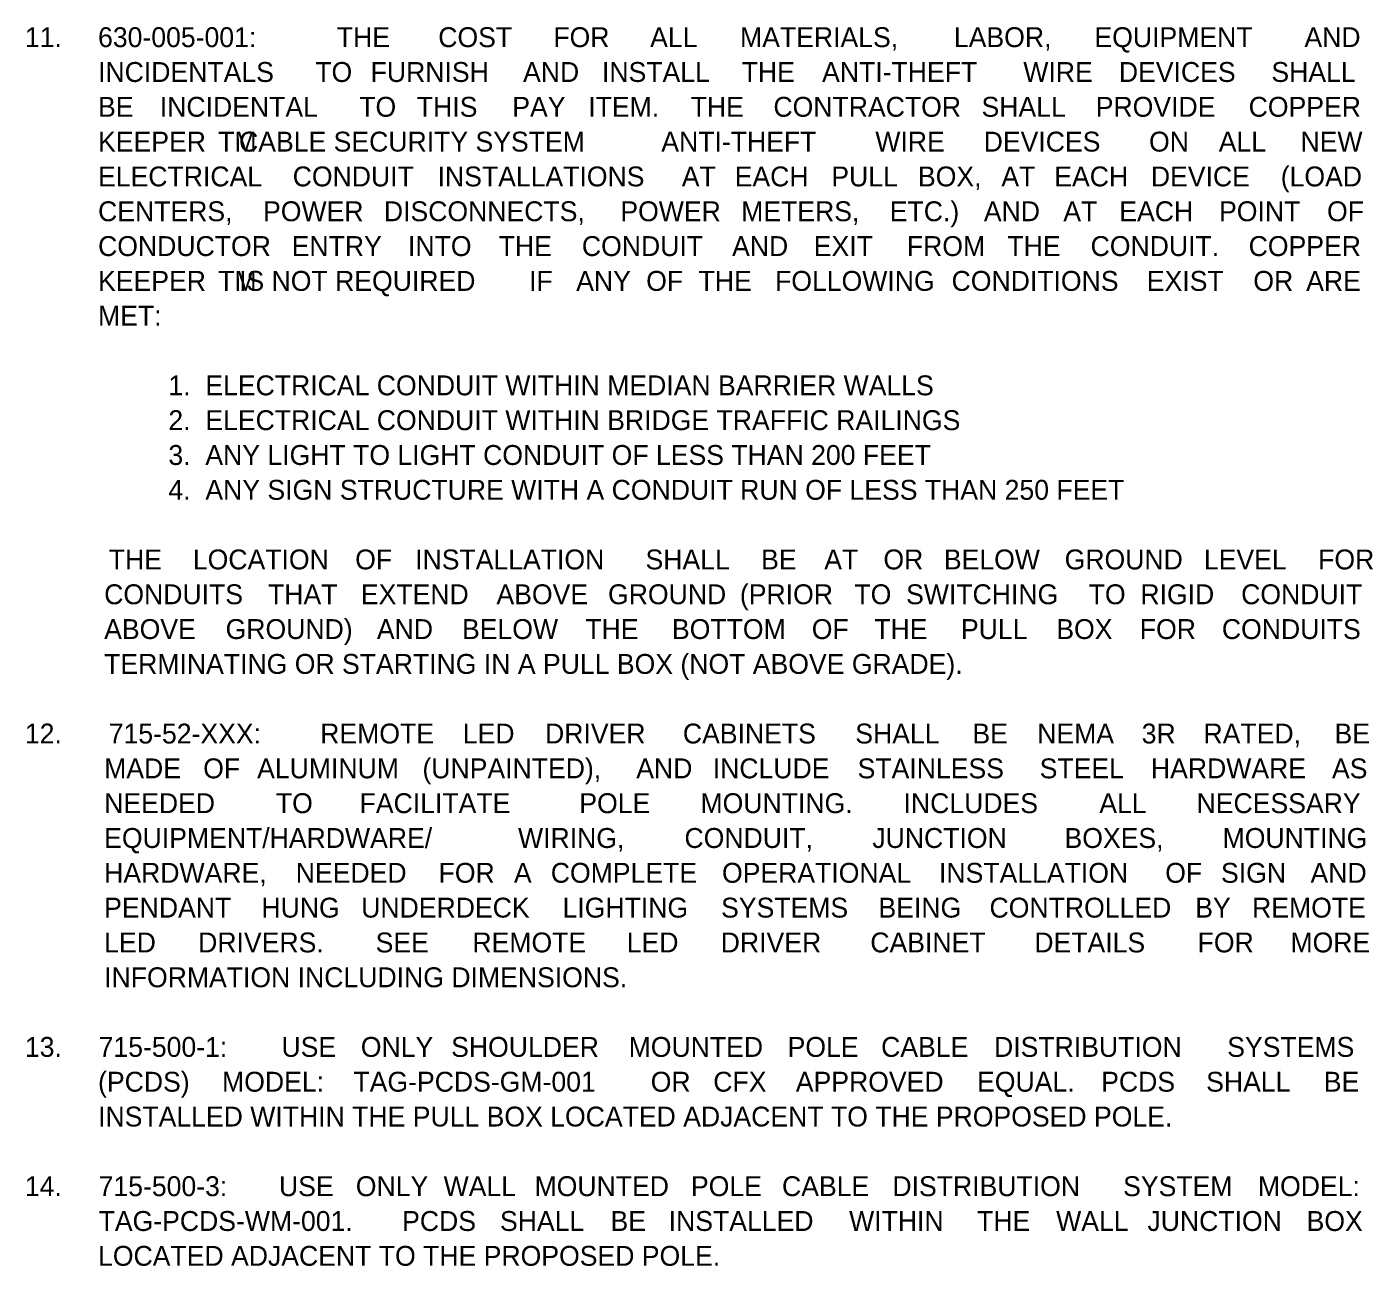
# Model space of a CAD drawing. Extents: x -55 to 2471539, y -90 to 3608906.
# Drawn here: x 543.9 to 1017.8, y 2936.3 to 3372.3 of the extents above; entities that cross this region are included whole.
import ezdxf

# ---------------------------------------------------------------- set-up
doc = ezdxf.new("R2010")
doc.units = 0
doc.layers.add('XSCell', color=7, linetype='Continuous')

msp = doc.modelspace()

# ---------------------------------------------------------------- texts
at = {"layer": 'XSCell'}
for s, p in [('11.', (543.22, 3365.2)), ('630-005-001: ', (568.97, 3365.2)), ('THE ', (653.02, 3365.2)), ('COST ', (688.72, 3365.2)), ('FOR ', (729.23, 3365.2)), ('ALL ', (763.31, 3365.2)), ('MATERIALS, ', (794.95, 3365.2)), ('LABOR, ', (870.23, 3365.2)), ('EQUIPMENT ', (919.7, 3365.2)), ('AND ', (993.61, 3365.2)), ('INCIDENTALS ', (568.97, 3352.95)), ('TO ', (645.44, 3352.95)), ('FURNISH ', (664.92, 3352.95)), ('AND ', (718.57, 3352.95)), ('INSTALL ', (746.35, 3352.95)), ('THE ', (795.52, 3352.95)), ('ANTI-THEFT ', (823.83, 3352.95)), ('WIRE ', (894.66, 3352.95)), ('DEVICES ', (928.3, 3352.95)), ('SHALL ', (981.99, 3352.95)), ('BE ', (568.97, 3340.7)), ('INCIDENTAL ', (590.71, 3340.7)), ('TO ', (660.91, 3340.7)), ('THIS ', (681.19, 3340.7)), ('PAY ', (714.78, 3340.7)), ('ITEM. ', (741.52, 3340.7)), ('THE ', (777.58, 3340.7)), ('CONTRACTOR ', (806.7, 3340.7)), ('SHALL ', (879.95, 3340.7)), ('PROVIDE ', (920.15, 3340.7)), ('COPPER ', (973.98, 3340.7)), ('KEEPER', (568.97, 3328.45)), ('TM', (611.26, 3328.45)), (' CABLE SECURITY SYSTEM ', (616, 3328.45)), ('ANTI-THEFT ', (767.23, 3328.45)), ('WIRE ', (842.57, 3328.45)), ('DEVICES ', (880.71, 3328.45)), ('ON ', (938.91, 3328.45)), ('ALL ', (963.46, 3328.45)), ('NEW ', (992.22, 3328.45)), ('ELECTRICAL ', (568.97, 3316.2)), ('CONDUIT ', (637.48, 3316.2)), ('INSTALLATIONS ', (688.48, 3316.2)), ('AT ', (774.45, 3316.2)), ('EACH ', (793.07, 3316.2)), ('PULL ', (827.08, 3316.2)), ('BOX, ', (857.58, 3316.2)), ('AT ', (886.94, 3316.2)), ('EACH ', (905.56, 3316.2)), ('DEVICE ', (939.57, 3316.2)), ('(LOAD ', (985.28, 3316.2)), ('CENTERS, ', (568.97, 3303.95)), ('POWER ', (627.05, 3303.95)), ('DISCONNECTS, ', (669.58, 3303.95)), ('POWER ', (752.82, 3303.95)), ('METERS, ', (795.35, 3303.95)), ('ETC.) ', (847.66, 3303.95)), ('AND ', (880.77, 3303.95)), ('AT ', (908.74, 3303.95)), ('EACH ', (928.45, 3303.95)), ('POINT ', (963.56, 3303.95)), ('OF ', (1001.57, 3303.95)), ('CONDUCTOR ', (568.97, 3291.7)), ('ENTRY ', (637.12, 3291.7)), ('INTO ', (678.08, 3291.7)), ('THE ', (709.99, 3291.7)), ('CONDUIT ', (739.28, 3291.7)), ('AND ', (792.15, 3291.7)), ('EXIT ', (820.9, 3291.7)), ('FROM ', (853.67, 3291.7)), ('THE ', (889.06, 3291.7)), ('CONDUIT. ', (918.35, 3291.7)), ('COPPER ', (973.98, 3291.7)), ('KEEPER', (568.97, 3279.45)), ('TM', (611.26, 3279.45)), (' IS NOT REQUIRED ', (616, 3279.45)), ('IF ', (720.68, 3279.45)), ('ANY ', (737.28, 3279.45)), ('OF ', (761.91, 3279.45)), ('THE ', (780.35, 3279.45)), ('FOLLOWING ', (807.28, 3279.45)), ('CONDITIONS ', (869.42, 3279.45)), ('EXIST ', (938.14, 3279.45)), ('OR ', (975.63, 3279.45)), ('ARE ', (994.23, 3279.45)), ('MET:', (568.97, 3267.2)), ('1.  ELECTRICAL CONDUIT WITHIN MEDIAN BARRIER WALLS', (593.73, 3242.7)), ('2.  ELECTRICAL CONDUIT WITHIN BRIDGE TRAFFIC RAILINGS', (593.73, 3230.45)), ('3.  ANY LIGHT TO LIGHT CONDUIT OF LESS THAN 200 FEET ', (593.73, 3218.2)), ('4.  ANY SIGN STRUCTURE WITH A CONDUIT RUN OF LESS THAN 250 FEET', (593.73, 3205.95)), ('THE ', (572.73, 3181.45)), ('LOCATION ', (602.34, 3181.45)), ('OF ', (659.48, 3181.45)), ('INSTALLATION ', (680.59, 3181.45)), ('SHALL ', (761.68, 3181.45)), ('BE ', (802.37, 3181.45)), ('AT ', (824.61, 3181.45)), ('OR ', (845.42, 3181.45)), ('BELOW ', (866.7, 3181.45)), ('GROUND ', (909.21, 3181.45)), ('LEVEL ', (958.23, 3181.45)), ('FOR ', (998.45, 3181.45)), ('CONDUITS ', (571.12, 3169.2)), ('THAT ', (628.8, 3169.2)), ('EXTEND ', (661.48, 3169.2)), ('ABOVE ', (709.21, 3169.2)), ('GROUND ', (748.48, 3169.2)), ('(PRIOR ', (794.9, 3169.2)), ('TO ', (835.21, 3169.2)), ('SWITCHING ', (853.4, 3169.2)), ('TO ', (917.68, 3169.2)), ('RIGID ', (935.87, 3169.2)), ('CONDUIT ', (971.34, 3169.2)), ('ABOVE ', (571.12, 3156.95)), ('GROUND) ', (613.87, 3156.95)), ('AND ', (667.12, 3156.95)), ('BELOW ', (697.08, 3156.95)), ('THE ', (740.49, 3156.95)), ('BOTTOM ', (770.98, 3156.95)), ('OF ', (820.2, 3156.95)), ('THE ', (842.2, 3156.95)), ('PULL ', (872.7, 3156.95)), ('BOX ', (906.28, 3156.95)), ('FOR ', (935.67, 3156.95)), ('CONDUITS ', (964.56, 3156.95)), ('TERMINATING OR STARTING IN A PULL BOX (NOT ABOVE GRADE).  ', (571.12, 3144.7)), ('12.', (543.22, 3120.2)), ('715-52-XXX: ', (572.73, 3120.2)), ('REMOTE ', (647.17, 3120.2)), ('LED ', (697.36, 3120.2)), ('DRIVER ', (726.31, 3120.2)), ('CABINETS ', (774.83, 3120.2)), ('SHALL ', (835.52, 3120.2)), ('BE ', (876.75, 3120.2)), ('NEMA ', (899.55, 3120.2)), ('3R ', (936.34, 3120.2)), ('RATED, ', (958.08, 3120.2)), ('BE ', (1004.21, 3120.2)), ('MADE ', (571.12, 3107.95)), ('OF ', (605.98, 3107.95)), ('ALUMINUM ', (624.96, 3107.95)), ('(UNPAINTED), ', (683.15, 3107.95)), ('AND ', (758.41, 3107.95)), ('INCLUDE ', (785.34, 3107.95)), ('STAINLESS ', (836.34, 3107.95)), ('STEEL ', (900.42, 3107.95)), ('HARDWARE ', (939.58, 3107.95)), ('AS ', (1003.31, 3107.95)), ('NEEDED ', (571.12, 3095.7)), ('TO ', (631.56, 3095.7)), ('FACILITATE ', (661.04, 3095.7)), ('POLE ', (738.37, 3095.7)), ('MOUNTING. ', (781.02, 3095.7)), ('INCLUDES ', (852.5, 3095.7)), ('ALL ', (921.41, 3095.7)), ('NECESSARY ', (955.65, 3095.7)), ('EQUIPMENT/HARDWARE/ ', (571.12, 3083.45)), ('WIRING, ', (716.8, 3083.45)), ('CONDUIT, ', (775.39, 3083.45)), ('JUNCTION ', (841.51, 3083.45)), ('BOXES, ', (909.17, 3083.45)), ('MOUNTING ', (964.81, 3083.45)), ('HARDWARE, ', (571.12, 3071.2)), ('NEEDED ', (638.56, 3071.2)), ('FOR ', (688.84, 3071.2)), ('A ', (715.36, 3071.2)), ('COMPLETE ', (728.33, 3071.2)), ('OPERATIONAL ', (788.6, 3071.2)), ('INSTALLATION ', (864.99, 3071.2)), ('OF ', (944.61, 3071.2)), ('SIGN ', (964.25, 3071.2)), ('AND ', (995.76, 3071.2)), ('PENDANT ', (571.12, 3058.95)), ('HUNG ', (626.47, 3058.95)), ('UNDERDECK ', (661.59, 3058.95)), ('LIGHTING ', (732.47, 3058.95)), ('SYSTEMS ', (788.28, 3058.95)), ('BEING ', (843.68, 3058.95)), ('CONTROLLED ', (882.77, 3058.95)), ('BY ', (955.18, 3058.95)), ('REMOTE ', (975.19, 3058.95)), ('LED ', (571.12, 3046.7)), ('DRIVERS. ', (604.2, 3046.7)), ('SEE ', (666.68, 3046.7)), ('REMOTE ', (700.74, 3046.7)), ('LED ', (755.07, 3046.7)), ('DRIVER ', (788.15, 3046.7)), ('CABINET ', (840.8, 3046.7)), ('DETAILS ', (898.54, 3046.7)), ('FOR ', (956.02, 3046.7)), ('MORE ', (988.7, 3046.7)), ('INFORMATION INCLUDING DIMENSIONS. ', (571.12, 3034.45)), ('13.', (543.22, 3009.95)), ('715-500-1: ', (569.17, 3009.95)), ('USE ', (633.53, 3009.95)), ('ONLY ', (661.46, 3009.95)), ('SHOULDER ', (693.26, 3009.95)), ('MOUNTED ', (755.74, 3009.95)), ('POLE ', (811.69, 3009.95)), ('CABLE ', (844.61, 3009.95)), ('DISTRIBUTION ', (884.36, 3009.95)), ('SYSTEMS ', (966.44, 3009.95)), ('(PCDS) ', (568.97, 2997.7)), ('MODEL: ', (612.62, 2997.7)), ('TAG-PCDS-GM-001 ', (658.87, 2997.7)), ('OR ', (763.51, 2997.7)), ('CFX ', (785.52, 2997.7)), ('APPROVED ', (814.58, 2997.7)), ('EQUAL. ', (878.38, 2997.7)), ('PCDS ', (922.07, 2997.7)), ('SHALL ', (959.02, 2997.7)), ('BE ', (1000.44, 2997.7)), ('INSTALLED WITHIN THE PULL BOX LOCATED ADJACENT TO THE PROPOSED POLE.', (568.97, 2985.45)), ('14.', (543.22, 2960.95)), ('715-500-3: ', (569.17, 2960.95)), ('USE ', (632.65, 2960.95)), ('ONLY ', (659.7, 2960.95)), ('WALL ', (690.61, 2960.95)), ('MOUNTED ', (722.61, 2960.95)), ('POLE ', (777.67, 2960.95)), ('CABLE ', (809.72, 2960.95)), ('DISTRIBUTION ', (848.58, 2960.95)), ('SYSTEM ', (929.79, 2960.95)), ('MODEL: ', (977.24, 2960.95)), ('TAG-PCDS-WM-001. ', (569.17, 2948.7)), ('PCDS ', (676, 2948.7)), ('SHALL ', (710.45, 2948.7)), ('BE ', (749.36, 2948.7)), ('INSTALLED ', (769.83, 2948.7)), ('WITHIN ', (833.34, 2948.7)), ('THE ', (878.39, 2948.7)), ('WALL ', (906.22, 2948.7)), ('JUNCTION ', (938.35, 2948.7)), ('BOX ', (994.38, 2948.7)), ('LOCATED ADJACENT TO THE PROPOSED POLE.', (568.97, 2936.45))]:
    msp.add_text(s, height=7, dxfattribs=at).set_placement(p)

doc.saveas('drawing.dxf')
